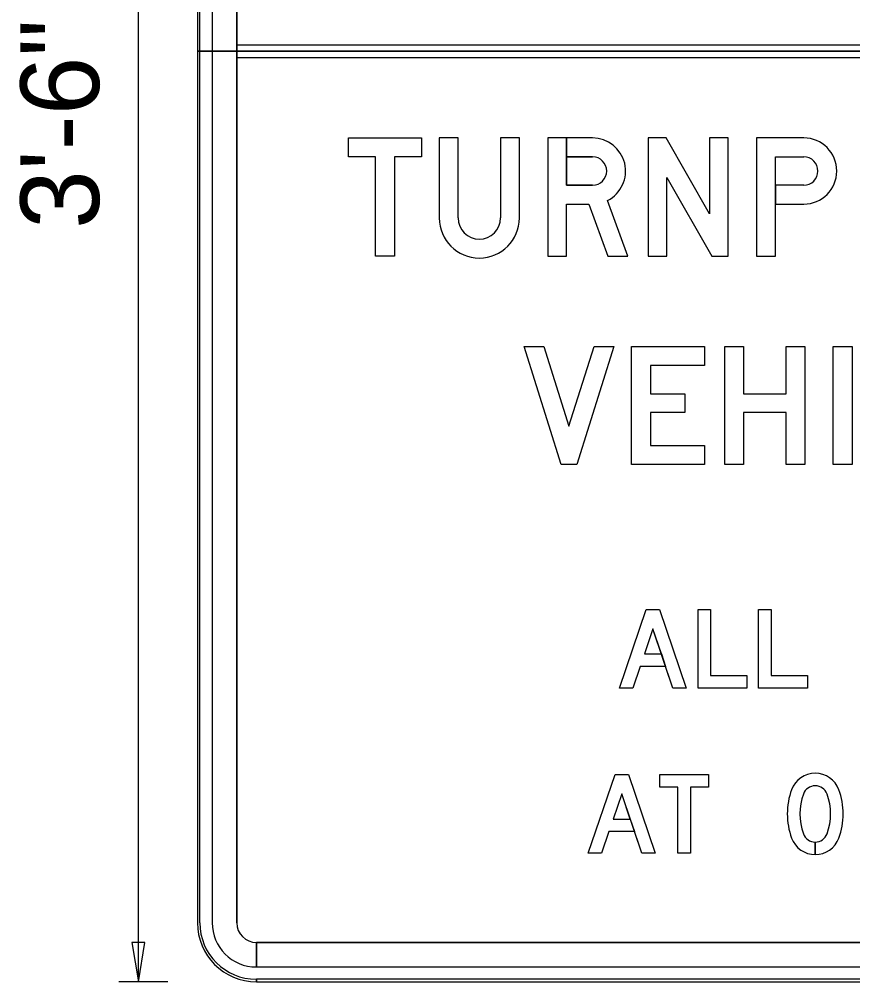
# Model space of a CAD drawing. Extents: x 17890071 to 17890754, y 17897628 to 17897992.
# Drawn here: x 17890192.86 to 17890198.75, y 17897850.83 to 17897857.62 of the extents above; entities that cross this region are included whole.
import ezdxf

# ---------------------------------------------------------------- set-up
doc = ezdxf.new("R2010")
doc.units = 0
for name, color, linetype in [('GSBWFill', 7, 'Continuous'), ('GSColorFill', 7, 'Continuous'), ('GSDims', 7, 'Continuous'), ('GSOutline', 7, 'Continuous')]:
    doc.layers.add(name, color=color, linetype=linetype)

msp = doc.modelspace()

# ---------------------------------------------------------------- linework, layer by layer
at = {"layer": 'GSBWFill'}
for p, q in [((17890194.1207, 17897862.079), (17890194.1207, 17897851.2456)), ((17890194.2249, 17897862.079), (17890194.2249, 17897851.2456)), ((17890194.3985, 17897851.2456), (17890194.3985, 17897862.079)), ((17890194.3985, 17897857.4418), (17890194.3985, 17897857.355)), ((17890207.1763, 17897857.4418), (17890194.3985, 17897857.4418)), ((17890194.3985, 17897857.355), (17890207.1763, 17897857.355)), ((17890195.829, 17897856.7864), (17890195.829, 17897856.2218)), ((17890198.204, 17897856.6531), (17890198.404, 17897856.6531)), ((17890198.4851, 17897851.7266), (17890198.4851, 17897851.8155)), ((17890198.4851, 17897851.8155), (17890198.4851, 17897851.7266)), ((17890194.5374, 17897850.9331), (17890194.5374, 17897851.1067)), ((17890207.0374, 17897851.1067), (17890194.5391, 17897851.1067)), ((17890194.5391, 17897851.1067), (17890194.5391, 17897850.9331)), ((17890194.5391, 17897850.9331), (17890207.0374, 17897850.9331)), ((17890194.5374, 17897850.8289), (17890207.0374, 17897850.8289))]:
    msp.add_line(p, q, dxfattribs=at)
for points in [[(17890195.704, 17897856.7864), (17890195.704, 17897856.6531), (17890195.5124, 17897856.6531), (17890195.5124, 17897855.9531), (17890195.379, 17897855.9531), (17890195.379, 17897856.6531), (17890195.1874, 17897856.6531), (17890195.1874, 17897856.7864)], [(17890197.8707, 17897855.9531), (17890197.8707, 17897856.7864), (17890197.7374, 17897856.7864), (17890197.7374, 17897856.251), (17890197.4314, 17897856.7864), (17890197.304, 17897856.7864), (17890197.304, 17897855.9531), (17890197.4374, 17897855.9531), (17890197.4374, 17897856.5072), (17890197.754, 17897855.9531)], [(17890196.5688, 17897855.3142), (17890196.7457, 17897854.7527), (17890196.9226, 17897855.3142), (17890197.0624, 17897855.3142), (17890196.7999, 17897854.4809), (17890196.6915, 17897854.4809), (17890196.429, 17897855.3142)], [(17890197.704, 17897855.1809), (17890197.3207, 17897855.1809), (17890197.3207, 17897854.9809), (17890197.563, 17897854.9809), (17890197.563, 17897854.8475), (17890197.3207, 17897854.8475), (17890197.3207, 17897854.6142), (17890197.704, 17897854.6142), (17890197.704, 17897854.4809), (17890197.1874, 17897854.4809), (17890197.1874, 17897855.3142), (17890197.704, 17897855.3142)], [(17890197.8457, 17897855.3142), (17890197.979, 17897855.3142), (17890197.979, 17897854.9809), (17890198.279, 17897854.9809), (17890198.279, 17897855.3142), (17890198.4124, 17897855.3142), (17890198.4124, 17897854.4809), (17890198.279, 17897854.4809), (17890198.279, 17897854.8475), (17890197.979, 17897854.8475), (17890197.979, 17897854.4809), (17890197.8457, 17897854.4809)], [(17890198.6124, 17897855.3142), (17890198.7457, 17897855.3142), (17890198.7457, 17897854.4809), (17890198.6124, 17897854.4809)], [(17890197.1019, 17897852.9017), (17890197.2908, 17897853.4572), (17890197.3852, 17897853.4572), (17890197.5741, 17897852.9017), (17890197.4802, 17897852.9017), (17890197.338, 17897853.32), (17890197.2779, 17897853.1433), (17890197.398, 17897853.1433), (17890197.4282, 17897853.0544), (17890197.2477, 17897853.0544), (17890197.1957, 17897852.9017)], [(17890197.7463, 17897852.9906), (17890198.0019, 17897852.9906), (17890198.0019, 17897852.9017), (17890197.6574, 17897852.9017), (17890197.6574, 17897853.4572), (17890197.7463, 17897853.4572)], [(17890198.1741, 17897852.9906), (17890198.4296, 17897852.9906), (17890198.4296, 17897852.9017), (17890198.0852, 17897852.9017), (17890198.0852, 17897853.4572), (17890198.1741, 17897853.4572)], [(17890196.8823, 17897851.7363), (17890197.0712, 17897852.2919), (17890197.1656, 17897852.2919), (17890197.3545, 17897851.7363), (17890197.2606, 17897851.7363), (17890197.1184, 17897852.1546), (17890197.0583, 17897851.9779), (17890197.1785, 17897851.9779), (17890197.2087, 17897851.8891), (17890197.0281, 17897851.8891), (17890196.9762, 17897851.7363)], [(17890197.7323, 17897852.2919), (17890197.7323, 17897852.203), (17890197.6045, 17897852.203), (17890197.6045, 17897851.7363), (17890197.5156, 17897851.7363), (17890197.5156, 17897852.203), (17890197.3879, 17897852.203), (17890197.3879, 17897852.2919)]]:
    msp.add_lwpolyline(points, close=True, dxfattribs=at)
for points in [[(17890195.9624, 17897856.2218), (17890195.9624, 17897856.7864), (17890195.829, 17897856.7864)], [(17890196.3957, 17897856.2218), (17890196.3957, 17897856.7864), (17890196.2624, 17897856.7864), (17890196.2624, 17897856.2218)], [(17890196.9122, 17897856.4531), (17890196.729, 17897856.4531), (17890196.729, 17897856.7864), (17890196.5957, 17897856.7864), (17890196.5957, 17897855.9531), (17890196.729, 17897855.9531), (17890196.729, 17897856.3197), (17890196.8855, 17897856.3197), (17890197.0203, 17897855.9531), (17890197.1624, 17897855.9531), (17890197.0182, 17897856.3452)], [(17890196.729, 17897856.7864), (17890196.729, 17897856.6531), (17890196.9122, 17897856.6531)], [(17890196.9122, 17897856.7864), (17890196.729, 17897856.7864)], [(17890198.404, 17897856.7864), (17890198.0707, 17897856.7864), (17890198.0707, 17897855.9531), (17890198.204, 17897855.9531), (17890198.204, 17897856.6531)], [(17890198.404, 17897856.4531), (17890198.2041, 17897856.4531), (17890198.2041, 17897856.3197), (17890198.404, 17897856.3197)]]:
    msp.add_lwpolyline(points, dxfattribs=at)
for centre, radius, start, end in [((17890198.404, 17897856.5531), 0.2333, 270, 90), ((17890198.404, 17897856.5531), 0.1, 270, 90), ((17890196.1124, 17897856.2218), 0.2833, 180, 0), ((17890196.1124, 17897856.2218), 0.15, 180, 0), ((17890194.5374, 17897851.2456), 0.4167, 180, 270), ((17890194.5374, 17897851.2456), 0.3125, 180, 270), ((17890194.5374, 17897851.2456), 0.1389, 180, 270)]:
    msp.add_arc(centre, radius, start, end, dxfattribs=at)
for centre, major_axis, ratio, start_param, end_param in [((17890196.9122, 17897856.5531), (0, 0.2333), 0.999993, 3.613317, 6.283185), ((17890196.9122, 17897856.5531), (0, 0.1), 0.999993, 3.141593, 6.283185), ((17890198.4851, 17897852.1238), (0, 0.1778), 0.999998, 5.063177, 7.503193), ((17890198.4851, 17897852.1238), (0, 0.0889), 0.999998, 5.063177, 7.503193), ((17890198.7849, 17897852.0141), (0, 0.4971), 0.999998, 1.220008, 1.921585), ((17890198.7849, 17897852.0141), (0, 0.4082), 0.999998, 1.220008, 1.921585), ((17890198.1852, 17897852.0141), (0, 0.4082), 0.999998, 4.361601, 5.063177), ((17890198.1852, 17897852.0141), (0, 0.4971), 0.999998, 4.361601, 5.063177), ((17890198.4851, 17897851.9044), (0, 0.0889), 0.999998, 1.921585, 3.141593), ((17890198.4851, 17897851.9044), (0, 0.0889), 0.999998, 3.141905, 4.361601), ((17890198.4851, 17897851.9044), (0, 0.1778), 0.999998, 1.921585, 3.141593), ((17890198.4851, 17897851.9044), (0, 0.1778), 0.999998, 3.141749, 4.361601)]:
    msp.add_ellipse(centre, major_axis=major_axis, ratio=ratio, start_param=start_param, end_param=end_param, dxfattribs=at)
at = {"layer": 'GSColorFill'}
for p, q in [((17890194.1207, 17897862.079), (17890194.1207, 17897857.3984)), ((17890194.1207, 17897862.079), (17890194.1207, 17897851.2456)), ((17890194.1381, 17897851.2456), (17890194.1381, 17897862.079)), ((17890194.2249, 17897862.079), (17890194.2249, 17897851.2456)), ((17890194.3985, 17897851.2456), (17890194.3985, 17897862.079)), ((17890194.3985, 17897857.4418), (17890194.3985, 17897857.355)), ((17890207.1763, 17897857.4418), (17890194.3985, 17897857.4418)), ((17890207.4541, 17897857.3984), (17890194.1207, 17897857.3984)), ((17890194.1207, 17897857.3984), (17890194.1207, 17897851.2456)), ((17890194.1207, 17897857.3984), (17890207.4541, 17897857.3984)), ((17890194.3985, 17897857.355), (17890207.1763, 17897857.355)), ((17890195.829, 17897856.7864), (17890195.829, 17897856.2218)), ((17890198.204, 17897856.6531), (17890198.404, 17897856.6531)), ((17890198.4851, 17897851.7266), (17890198.4851, 17897851.8155)), ((17890198.4851, 17897851.8155), (17890198.4851, 17897851.7266)), ((17890194.5374, 17897850.9331), (17890194.5374, 17897851.1067)), ((17890207.0374, 17897851.1067), (17890194.5391, 17897851.1067)), ((17890194.5391, 17897851.1067), (17890194.5391, 17897850.9331)), ((17890194.5391, 17897850.9331), (17890207.0374, 17897850.9331)), ((17890194.5374, 17897850.8289), (17890194.5374, 17897850.8463)), ((17890207.0374, 17897850.8463), (17890194.5375, 17897850.8463)), ((17890194.5375, 17897850.8463), (17890194.5375, 17897850.8289)), ((17890194.5374, 17897850.8289), (17890207.0374, 17897850.8289)), ((17890194.5375, 17897850.8289), (17890207.0374, 17897850.8289))]:
    msp.add_line(p, q, dxfattribs=at)
for points in [[(17890195.704, 17897856.7864), (17890195.704, 17897856.6531), (17890195.5124, 17897856.6531), (17890195.5124, 17897855.9531), (17890195.379, 17897855.9531), (17890195.379, 17897856.6531), (17890195.1874, 17897856.6531), (17890195.1874, 17897856.7864)], [(17890197.8707, 17897855.9531), (17890197.8707, 17897856.7864), (17890197.7374, 17897856.7864), (17890197.7374, 17897856.251), (17890197.4314, 17897856.7864), (17890197.304, 17897856.7864), (17890197.304, 17897855.9531), (17890197.4374, 17897855.9531), (17890197.4374, 17897856.5072), (17890197.754, 17897855.9531)], [(17890196.5688, 17897855.3142), (17890196.7457, 17897854.7527), (17890196.9226, 17897855.3142), (17890197.0624, 17897855.3142), (17890196.7999, 17897854.4809), (17890196.6915, 17897854.4809), (17890196.429, 17897855.3142)], [(17890197.704, 17897855.1809), (17890197.3207, 17897855.1809), (17890197.3207, 17897854.9809), (17890197.563, 17897854.9809), (17890197.563, 17897854.8475), (17890197.3207, 17897854.8475), (17890197.3207, 17897854.6142), (17890197.704, 17897854.6142), (17890197.704, 17897854.4809), (17890197.1874, 17897854.4809), (17890197.1874, 17897855.3142), (17890197.704, 17897855.3142)], [(17890197.8457, 17897855.3142), (17890197.979, 17897855.3142), (17890197.979, 17897854.9809), (17890198.279, 17897854.9809), (17890198.279, 17897855.3142), (17890198.4124, 17897855.3142), (17890198.4124, 17897854.4809), (17890198.279, 17897854.4809), (17890198.279, 17897854.8475), (17890197.979, 17897854.8475), (17890197.979, 17897854.4809), (17890197.8457, 17897854.4809)], [(17890198.6124, 17897855.3142), (17890198.7457, 17897855.3142), (17890198.7457, 17897854.4809), (17890198.6124, 17897854.4809)], [(17890197.1019, 17897852.9017), (17890197.2908, 17897853.4572), (17890197.3852, 17897853.4572), (17890197.5741, 17897852.9017), (17890197.4802, 17897852.9017), (17890197.338, 17897853.32), (17890197.2779, 17897853.1433), (17890197.398, 17897853.1433), (17890197.4282, 17897853.0544), (17890197.2477, 17897853.0544), (17890197.1957, 17897852.9017)], [(17890197.7463, 17897852.9906), (17890198.0019, 17897852.9906), (17890198.0019, 17897852.9017), (17890197.6574, 17897852.9017), (17890197.6574, 17897853.4572), (17890197.7463, 17897853.4572)], [(17890198.1741, 17897852.9906), (17890198.4296, 17897852.9906), (17890198.4296, 17897852.9017), (17890198.0852, 17897852.9017), (17890198.0852, 17897853.4572), (17890198.1741, 17897853.4572)], [(17890196.8823, 17897851.7363), (17890197.0712, 17897852.2919), (17890197.1656, 17897852.2919), (17890197.3545, 17897851.7363), (17890197.2606, 17897851.7363), (17890197.1184, 17897852.1546), (17890197.0583, 17897851.9779), (17890197.1785, 17897851.9779), (17890197.2087, 17897851.8891), (17890197.0281, 17897851.8891), (17890196.9762, 17897851.7363)], [(17890197.7323, 17897852.2919), (17890197.7323, 17897852.203), (17890197.6045, 17897852.203), (17890197.6045, 17897851.7363), (17890197.5156, 17897851.7363), (17890197.5156, 17897852.203), (17890197.3879, 17897852.203), (17890197.3879, 17897852.2919)]]:
    msp.add_lwpolyline(points, close=True, dxfattribs=at)
for points in [[(17890195.9624, 17897856.2218), (17890195.9624, 17897856.7864), (17890195.829, 17897856.7864)], [(17890196.3957, 17897856.2218), (17890196.3957, 17897856.7864), (17890196.2624, 17897856.7864), (17890196.2624, 17897856.2218)], [(17890196.9122, 17897856.4531), (17890196.729, 17897856.4531), (17890196.729, 17897856.7864), (17890196.5957, 17897856.7864), (17890196.5957, 17897855.9531), (17890196.729, 17897855.9531), (17890196.729, 17897856.3197), (17890196.8855, 17897856.3197), (17890197.0203, 17897855.9531), (17890197.1624, 17897855.9531), (17890197.0182, 17897856.3452)], [(17890196.729, 17897856.7864), (17890196.729, 17897856.6531), (17890196.9122, 17897856.6531)], [(17890196.9122, 17897856.7864), (17890196.729, 17897856.7864)], [(17890198.404, 17897856.7864), (17890198.0707, 17897856.7864), (17890198.0707, 17897855.9531), (17890198.204, 17897855.9531), (17890198.204, 17897856.6531)], [(17890198.404, 17897856.4531), (17890198.2041, 17897856.4531), (17890198.2041, 17897856.3197), (17890198.404, 17897856.3197)]]:
    msp.add_lwpolyline(points, dxfattribs=at)
for centre, radius, start, end in [((17890198.404, 17897856.5531), 0.2333, 270, 90), ((17890198.404, 17897856.5531), 0.1, 270, 90), ((17890196.1124, 17897856.2218), 0.2833, 180, 0), ((17890196.1124, 17897856.2218), 0.15, 180, 0), ((17890194.5374, 17897851.2456), 0.4167, 180, 270), ((17890194.5374, 17897851.2456), 0.4167, 180, 270), ((17890194.5374, 17897851.2456), 0.3993, 180, 270), ((17890194.5374, 17897851.2456), 0.3125, 180, 270), ((17890194.5374, 17897851.2456), 0.1389, 180, 270)]:
    msp.add_arc(centre, radius, start, end, dxfattribs=at)
for centre, major_axis, ratio, start_param, end_param in [((17890196.9122, 17897856.5531), (0, 0.2333), 0.999993, 3.613317, 6.283185), ((17890196.9122, 17897856.5531), (0, 0.1), 0.999993, 3.141593, 6.283185), ((17890198.4851, 17897852.1238), (0, 0.1778), 0.999998, 5.063177, 7.503193), ((17890198.4851, 17897852.1238), (0, 0.0889), 0.999998, 5.063177, 7.503193), ((17890198.7849, 17897852.0141), (0, 0.4971), 0.999998, 1.220008, 1.921585), ((17890198.7849, 17897852.0141), (0, 0.4082), 0.999998, 1.220008, 1.921585), ((17890198.1852, 17897852.0141), (0, 0.4082), 0.999998, 4.361601, 5.063177), ((17890198.1852, 17897852.0141), (0, 0.4971), 0.999998, 4.361601, 5.063177), ((17890198.4851, 17897851.9044), (0, 0.0889), 0.999998, 1.921585, 3.141593), ((17890198.4851, 17897851.9044), (0, 0.0889), 0.999998, 3.141905, 4.361601), ((17890198.4851, 17897851.9044), (0, 0.1778), 0.999998, 1.921585, 3.141593), ((17890198.4851, 17897851.9044), (0, 0.1778), 0.999998, 3.141749, 4.361601)]:
    msp.add_ellipse(centre, major_axis=major_axis, ratio=ratio, start_param=start_param, end_param=end_param, dxfattribs=at)
at = {"layer": 'GSDims'}
for p, q in [((17890193.704, 17897850.8289), (17890193.704, 17897862.4957)), ((17890193.9124, 17897850.8289), (17890193.5651, 17897850.8289))]:
    msp.add_line(p, q, dxfattribs=at)
msp.add_lwpolyline([(17890193.704, 17897850.8289), (17890193.7503, 17897851.1067), (17890193.6577, 17897851.1067)], close=True, dxfattribs=at)
at = {"layer": 'GSOutline'}
for p, q in [((17890194.1207, 17897862.079), (17890194.1207, 17897851.2456)), ((17890194.2249, 17897862.079), (17890194.2249, 17897851.2456)), ((17890194.3985, 17897862.079), (17890194.3985, 17897851.2456)), ((17890194.3985, 17897857.4418), (17890194.3985, 17897857.355)), ((17890207.1763, 17897857.4418), (17890194.3985, 17897857.4418)), ((17890194.3985, 17897857.355), (17890207.1763, 17897857.355)), ((17890195.829, 17897856.7864), (17890195.829, 17897856.2218)), ((17890198.204, 17897856.3197), (17890198.404, 17897856.3197)), ((17890194.5374, 17897851.1067), (17890207.0374, 17897851.1067)), ((17890194.5374, 17897850.9331), (17890207.0374, 17897850.9331)), ((17890194.5374, 17897850.8289), (17890207.0374, 17897850.8289))]:
    msp.add_line(p, q, dxfattribs=at)
for points in [[(17890195.704, 17897856.7864), (17890195.704, 17897856.6531), (17890195.5124, 17897856.6531), (17890195.5124, 17897855.9531), (17890195.379, 17897855.9531), (17890195.379, 17897856.6531), (17890195.1874, 17897856.6531), (17890195.1874, 17897856.7864)], [(17890197.8707, 17897855.9531), (17890197.8707, 17897856.7864), (17890197.7374, 17897856.7864), (17890197.7374, 17897856.251), (17890197.4314, 17897856.7864), (17890197.304, 17897856.7864), (17890197.304, 17897855.9531), (17890197.4374, 17897855.9531), (17890197.4374, 17897856.5072), (17890197.754, 17897855.9531)], [(17890196.5688, 17897855.3142), (17890196.7457, 17897854.7527), (17890196.9226, 17897855.3142), (17890197.0624, 17897855.3142), (17890196.7999, 17897854.4809), (17890196.6915, 17897854.4809), (17890196.429, 17897855.3142)], [(17890197.704, 17897855.1809), (17890197.3207, 17897855.1809), (17890197.3207, 17897854.9809), (17890197.563, 17897854.9809), (17890197.563, 17897854.8475), (17890197.3207, 17897854.8475), (17890197.3207, 17897854.6142), (17890197.704, 17897854.6142), (17890197.704, 17897854.4809), (17890197.1874, 17897854.4809), (17890197.1874, 17897855.3142), (17890197.704, 17897855.3142)], [(17890197.8457, 17897855.3142), (17890197.979, 17897855.3142), (17890197.979, 17897854.9809), (17890198.279, 17897854.9809), (17890198.279, 17897855.3142), (17890198.4124, 17897855.3142), (17890198.4124, 17897854.4809), (17890198.279, 17897854.4809), (17890198.279, 17897854.8475), (17890197.979, 17897854.8475), (17890197.979, 17897854.4809), (17890197.8457, 17897854.4809)], [(17890198.6124, 17897855.3142), (17890198.7457, 17897855.3142), (17890198.7457, 17897854.4809), (17890198.6124, 17897854.4809)], [(17890197.2477, 17897853.0544), (17890197.1957, 17897852.9017), (17890197.1019, 17897852.9017), (17890197.2908, 17897853.4572), (17890197.3852, 17897853.4572), (17890197.5741, 17897852.9017), (17890197.4802, 17897852.9017), (17890197.4283, 17897853.0544)], [(17890197.7463, 17897852.9906), (17890198.0019, 17897852.9906), (17890198.0019, 17897852.9017), (17890197.6574, 17897852.9017), (17890197.6574, 17897853.4572), (17890197.7463, 17897853.4572)], [(17890198.1741, 17897852.9906), (17890198.4296, 17897852.9906), (17890198.4296, 17897852.9017), (17890198.0852, 17897852.9017), (17890198.0852, 17897853.4572), (17890198.1741, 17897853.4572)], [(17890197.2779, 17897853.1433), (17890197.398, 17897853.1433), (17890197.338, 17897853.32)], [(17890197.0281, 17897851.8891), (17890196.9762, 17897851.7363), (17890196.8823, 17897851.7363), (17890197.0712, 17897852.2919), (17890197.1656, 17897852.2919), (17890197.3545, 17897851.7363), (17890197.2606, 17897851.7363), (17890197.2087, 17897851.8891)], [(17890197.7323, 17897852.2919), (17890197.7323, 17897852.203), (17890197.6045, 17897852.203), (17890197.6045, 17897851.7363), (17890197.5156, 17897851.7363), (17890197.5156, 17897852.203), (17890197.3879, 17897852.203), (17890197.3879, 17897852.2919)], [(17890197.0583, 17897851.9779), (17890197.1785, 17897851.9779), (17890197.1184, 17897852.1546)]]:
    msp.add_lwpolyline(points, close=True, dxfattribs=at)
for points in [[(17890195.9624, 17897856.2218), (17890195.9624, 17897856.7864), (17890195.829, 17897856.7864)], [(17890196.3957, 17897856.2218), (17890196.3957, 17897856.7864), (17890196.2624, 17897856.7864), (17890196.2624, 17897856.2218)], [(17890196.9122, 17897856.7864), (17890196.5957, 17897856.7864), (17890196.5957, 17897855.9531), (17890196.729, 17897855.9531), (17890196.729, 17897856.3197), (17890196.8855, 17897856.3197), (17890197.0203, 17897855.9531), (17890197.1624, 17897855.9531), (17890197.0182, 17897856.3452)], [(17890198.404, 17897856.7864), (17890198.0707, 17897856.7864), (17890198.0707, 17897855.9531), (17890198.204, 17897855.9531), (17890198.204, 17897856.3197)], [(17890196.9122, 17897856.6531), (17890196.729, 17897856.6531), (17890196.729, 17897856.4531), (17890196.9122, 17897856.4531)], [(17890198.404, 17897856.4531), (17890198.204, 17897856.4531), (17890198.204, 17897856.6531), (17890198.404, 17897856.6531)]]:
    msp.add_lwpolyline(points, dxfattribs=at)
for centre, radius, start, end in [((17890198.404, 17897856.5531), 0.2333, 270, 90), ((17890198.404, 17897856.5531), 0.1, 270, 90), ((17890196.1124, 17897856.2218), 0.2833, 180, 0), ((17890196.1124, 17897856.2218), 0.15, 180, 0), ((17890194.5374, 17897851.2456), 0.4167, 180, 270), ((17890194.5374, 17897851.2456), 0.3125, 180, 270), ((17890194.5374, 17897851.2456), 0.1389, 180, 270)]:
    msp.add_arc(centre, radius, start, end, dxfattribs=at)
for centre, major_axis, ratio, start_param, end_param in [((17890196.9122, 17897856.5531), (0, 0.2333), 0.999993, 3.613317, 6.283185), ((17890196.9122, 17897856.5531), (0, 0.1), 0.999993, 3.141593, 6.283185), ((17890198.4851, 17897852.1238), (0, 0.1778), 0.999998, 5.063177, 7.503193), ((17890198.4851, 17897852.1238), (0, 0.0889), 0.999998, 5.063177, 7.503193), ((17890198.7849, 17897852.0141), (0, 0.4971), 0.999998, 1.220008, 1.921585), ((17890198.7849, 17897852.0141), (0, 0.4082), 0.999998, 1.220008, 1.921585), ((17890198.1852, 17897852.0141), (0, 0.4082), 0.999998, 4.361601, 5.063177), ((17890198.1852, 17897852.0141), (0, 0.4971), 0.999998, 4.361601, 5.063177), ((17890198.4851, 17897851.9044), (0, 0.0889), 0.999998, 1.921585, 4.361601), ((17890198.4851, 17897851.9044), (0, 0.1778), 0.999998, 1.921585, 4.361601)]:
    msp.add_ellipse(centre, major_axis=major_axis, ratio=ratio, start_param=start_param, end_param=end_param, dxfattribs=at)

# ---------------------------------------------------------------- texts
at = {"layer": 'GSDims'}
msp.add_text('3\'-6"', height=0.55556, rotation=90, dxfattribs=at).set_placement((17890193.4262, 17897856.1451))

doc.saveas('drawing.dxf')
